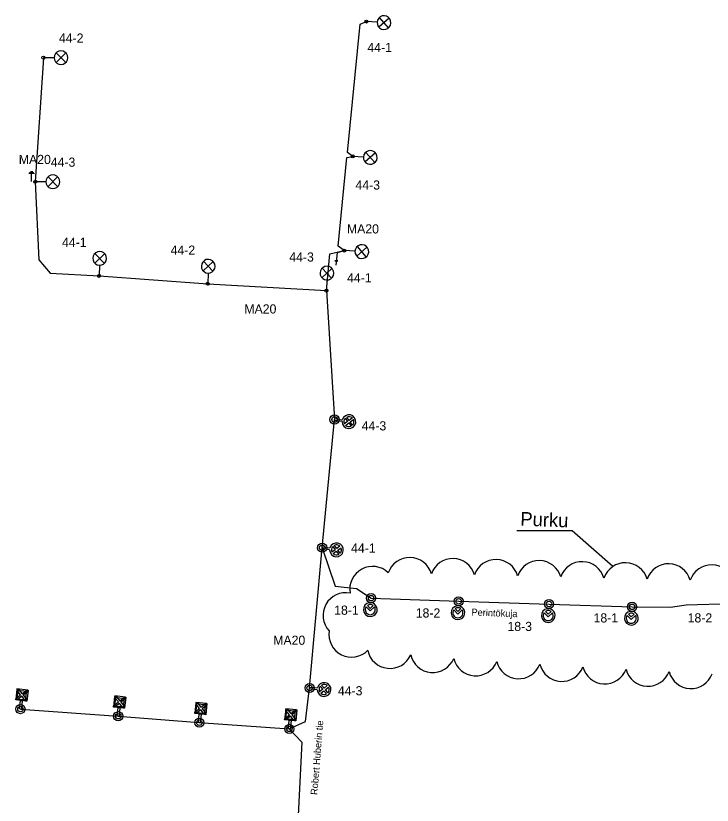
# Model space of a CAD drawing. Extents: x 25497851 to 25498523, y 6686544 to 6687372.
# Drawn here: x 25497851.1 to 25498079, y 6687110.6 to 6687368.9 of the extents above; entities that cross this region are included whole.
import ezdxf

# ---------------------------------------------------------------- set-up
doc = ezdxf.new("R2010")
doc.units = 0
for name, color, linetype in [('EL_CABLE_MAA', 7, 'Continuous'), ('KAAPELI', 7, 'Continuous'), ('KEYGWT_ANNOTATION', 7, 'Continuous'), ('Level 17', 7, 'Continuous'), ('Level 63', 7, 'Continuous'), ('MUU_SUUNNITELMAVIIVA', 7, 'Continuous'), ('PYLVAS', 7, 'Continuous'), ('Taso 1', 7, 'Continuous'), ('TEKSTI_SUUNNITELMA-ALUE', 7, 'Continuous'), ('VALAISIN', 7, 'Continuous'), ('VIITEVIIVA', 7, 'Continuous')]:
    doc.layers.add(name, color=color, linetype=linetype)

msp = doc.modelspace()

# ---------------------------------------------------------------- linework, layer by layer
at = {"layer": 'EL_CABLE_MAA'}
for points in [[(25497961.39, 6687322.89), (25497959.67, 6687324.13), (25497963.77, 6687366.17), (25497965.87, 6687367.01)], [(25497860.17, 6687355.18), (25497857.52, 6687314.58)], [(25497958.62, 6687292.08), (25497956.57, 6687293.5), (25497959.48, 6687322.57), (25497961.39, 6687322.89)], [(25497857.52, 6687314.58), (25497858.66, 6687289.03), (25497862.4, 6687284.66), (25497878.39, 6687283.78)], [(25497952.75, 6687278.97), (25497953.92, 6687291), (25497958.62, 6687292.08)], [(25497955.97, 6687287.26), (25497956.36, 6687291.42), (25497958.62, 6687292.08)], [(25497878.39, 6687283.78), (25497913.92, 6687281.21)], [(25497913.92, 6687281.21), (25497952.75, 6687278.97)], [(25497952.75, 6687278.97), (25497955.43, 6687236.8)], [(25497951.39, 6687194.86), (25497955.65, 6687182.29), (25497962.62, 6687181.52), (25497967.39, 6687178.33)], [(25497967.39, 6687178.33), (25497996.06, 6687177.32)], [(25497996.06, 6687177.32), (25498025.62, 6687176.4)], [(25498025.62, 6687176.4), (25498052.78, 6687175.51)], [(25498052.78, 6687175.51), (25498065.4, 6687175.42), (25498070.51, 6687176.14), (25498085.44, 6687176.58)]]:
    msp.add_lwpolyline(points, dxfattribs=at)
at = {"layer": 'KAAPELI'}
for p, q in [((25497951.39, 6687194.86), (25497955.43, 6687236.8)), ((25497947.28, 6687148.96), (25497951.39, 6687194.86)), ((25497852.66, 6687142.04), (25497884.63, 6687139.71)), ((25497884.63, 6687139.71), (25497911.19, 6687137.62)), ((25497911.19, 6687137.62), (25497940.63, 6687135.56))]:
    msp.add_line(p, q, dxfattribs=at)
for points in [[(25497940.63, 6687135.56), (25497945.95, 6687138.02), (25497947.28, 6687148.96)], [(25497940.63, 6687135.56), (25497944.75, 6687131.17), (25497943.46, 6687105.16)]]:
    msp.add_lwpolyline(points, dxfattribs=at)
at = {"layer": 'Level 17'}
for points in [[(25497855.37, 6687317.37), (25497856.31, 6687317.36)], [(25497855.66, 6687317.62), (25497856.33, 6687317.61)], [(25497856.33, 6687317.87), (25497855.96, 6687317.88)], [(25497856.28, 6687314.62), (25497856.32, 6687317.35)], [(25497856.31, 6687317.36), (25497857.26, 6687317.34)], [(25497856.71, 6687317.87), (25497856.33, 6687317.87)], [(25497856.33, 6687317.61), (25497857, 6687317.6)]]:
    msp.add_lwpolyline(points, dxfattribs=at)
at = {"layer": 'MUU_SUUNNITELMAVIIVA'}
for centre, start, end in [((25497980, 6687184.25), 16.1186, 161.1186), ((25497994.11, 6687183.91), 16.1119, 161.1119), ((25498008.23, 6687183.57), 16.1104, 161.1104), ((25498022.35, 6687183.23), 16.1096, 161.1096), ((25498036.46, 6687182.88), 16.1092, 161.1092), ((25497967.82, 6687181.35), 45.652, 190.652), ((25498050.58, 6687182.54), 16.1088, 161.1088), ((25498064.69, 6687182.2), 16.1085, 161.1085), ((25498078.81, 6687181.85), 16.1083, 161.1083), ((25497959.07, 6687172.73), 78.5211, 223.5211), ((25497961.01, 6687166.44), 170.7281, 315.7281), ((25497973.56, 6687162.74), 191.4587, 336.4587), ((25497987.57, 6687161.42), 192.7513, 337.7513), ((25498001.62, 6687160.33), 193.3921, 338.3921), ((25498015.69, 6687159.37), 193.7941, 338.7941), ((25498029.78, 6687158.49), 194.0765, 339.0765), ((25498043.87, 6687157.68), 194.2891, 339.2891), ((25498057.96, 6687156.91), 194.4565, 339.4565), ((25498072.05, 6687156.17), 194.5929, 339.5929)]:
    msp.add_arc(centre, 7.4, start, end, dxfattribs=at)
at = {"layer": 'PYLVAS'}
for centre, radius in [((25497955.43, 6687236.8), 1.5), ((25497955.43, 6687236.8), 0.9), ((25497951.39, 6687194.86), 1.5), ((25497951.39, 6687194.86), 0.9), ((25497967.39, 6687178.33), 1.5), ((25497967.39, 6687178.33), 0.9), ((25497996.06, 6687177.32), 1.5), ((25497996.06, 6687177.32), 0.9), ((25498025.6, 6687176.43), 1.5), ((25498025.6, 6687176.43), 0.9), ((25498052.78, 6687175.51), 1.5), ((25498052.78, 6687175.51), 0.9), ((25497947.28, 6687148.96), 1.5), ((25497947.28, 6687148.96), 0.9), ((25497852.66, 6687142.04), 1.5), ((25497852.66, 6687142.04), 0.9), ((25497884.63, 6687139.71), 1.5), ((25497884.63, 6687139.71), 0.9), ((25497911.19, 6687137.62), 1.5), ((25497911.19, 6687137.62), 0.9), ((25497940.63, 6687135.56), 1.5), ((25497940.63, 6687135.56), 0.9)]:
    msp.add_circle(centre, radius, dxfattribs=at)
at = {"layer": 'Taso 1'}
for p, q in [((25497973.08, 6687364.98), (25497970.14, 6687368.31)), ((25497969.36, 6687366.79), (25497965.87, 6687367.01)), ((25497973.27, 6687368.12), (25497969.94, 6687365.18)), ((25497867.49, 6687356.75), (25497864.35, 6687353.61)), ((25497867.49, 6687353.61), (25497864.35, 6687356.75)), ((25497863.67, 6687355.18), (25497860.17, 6687355.18)), ((25497964.88, 6687322.67), (25497961.39, 6687322.89)), ((25497968.79, 6687324), (25497965.46, 6687321.06)), ((25497968.6, 6687320.87), (25497965.66, 6687324.2)), ((25497861.02, 6687314.58), (25497857.52, 6687314.58)), ((25497864.84, 6687316.15), (25497861.7, 6687313)), ((25497864.84, 6687313), (25497861.7, 6687316.15)), ((25497965.83, 6687290.06), (25497962.89, 6687293.39)), ((25497880.19, 6687291.04), (25497876.95, 6687288)), ((25497877.05, 6687291.14), (25497880.1, 6687287.9)), ((25497962.12, 6687291.87), (25497958.62, 6687292.08)), ((25497966.03, 6687293.19), (25497962.7, 6687290.25)), ((25497915.72, 6687288.47), (25497912.48, 6687285.43)), ((25497912.58, 6687288.57), (25497915.62, 6687285.33)), ((25497955.49, 6687288.7), (25497956.46, 6687288.64)), ((25497955.5, 6687288.84), (25497956.47, 6687288.78)), ((25497878.5, 6687287.27), (25497878.39, 6687283.78)), ((25497954.55, 6687286.23), (25497951.31, 6687283.19)), ((25497951.41, 6687286.33), (25497954.45, 6687283.09)), ((25497914.03, 6687284.7), (25497913.92, 6687281.21)), ((25497952.86, 6687282.46), (25497952.75, 6687278.97))]:
    msp.add_line(p, q, dxfattribs=at)
for points in [[(25497973.85, 6687366.51), (25497973.79, 6687367.21), (25497973.51, 6687367.85), (25497973.04, 6687368.38), (25497972.43, 6687368.74), (25497971.75, 6687368.89), (25497971.05, 6687368.83), (25497970.4, 6687368.55), (25497969.87, 6687368.08), (25497969.52, 6687367.48), (25497969.36, 6687366.79), (25497969.43, 6687366.09), (25497969.71, 6687365.44), (25497970.17, 6687364.91), (25497970.78, 6687364.56), (25497971.47, 6687364.4), (25497972.17, 6687364.47), (25497972.81, 6687364.75), (25497973.34, 6687365.21), (25497973.7, 6687365.82)], [(25497868.17, 6687355.18), (25497868.06, 6687355.87), (25497867.74, 6687356.5), (25497867.24, 6687357), (25497866.62, 6687357.32), (25497865.92, 6687357.43), (25497865.23, 6687357.32), (25497864.6, 6687357), (25497864.1, 6687356.5), (25497863.78, 6687355.87), (25497863.67, 6687355.18), (25497863.78, 6687354.48), (25497864.1, 6687353.86), (25497864.6, 6687353.36), (25497865.23, 6687353.04), (25497865.92, 6687352.93), (25497866.62, 6687353.04), (25497867.24, 6687353.36), (25497867.74, 6687353.86), (25497868.06, 6687354.48)], [(25497969.37, 6687322.39), (25497969.3, 6687323.09), (25497969.02, 6687323.74), (25497968.56, 6687324.27), (25497967.95, 6687324.62), (25497967.27, 6687324.78), (25497966.57, 6687324.71), (25497965.92, 6687324.43), (25497965.39, 6687323.97), (25497965.03, 6687323.36), (25497964.88, 6687322.67), (25497964.95, 6687321.97), (25497965.23, 6687321.33), (25497965.69, 6687320.8), (25497966.3, 6687320.44), (25497966.98, 6687320.29), (25497967.68, 6687320.35), (25497968.33, 6687320.63), (25497968.86, 6687321.1), (25497969.22, 6687321.7)], [(25497865.52, 6687314.58), (25497865.41, 6687315.27), (25497865.09, 6687315.9), (25497864.59, 6687316.4), (25497863.96, 6687316.72), (25497863.27, 6687316.83), (25497862.57, 6687316.72), (25497861.95, 6687316.4), (25497861.45, 6687315.9), (25497861.13, 6687315.27), (25497861.02, 6687314.58), (25497861.13, 6687313.88), (25497861.45, 6687313.25), (25497861.95, 6687312.76), (25497862.57, 6687312.44), (25497863.27, 6687312.33), (25497863.96, 6687312.44), (25497864.59, 6687312.76), (25497865.09, 6687313.25), (25497865.41, 6687313.88)], [(25497966.61, 6687291.58), (25497966.54, 6687292.28), (25497966.26, 6687292.93), (25497965.8, 6687293.46), (25497965.19, 6687293.82), (25497964.5, 6687293.97), (25497963.8, 6687293.9), (25497963.16, 6687293.62), (25497962.63, 6687293.16), (25497962.27, 6687292.55), (25497962.12, 6687291.87), (25497962.18, 6687291.16), (25497962.46, 6687290.52), (25497962.93, 6687289.99), (25497963.53, 6687289.63), (25497964.22, 6687289.48), (25497964.92, 6687289.54), (25497965.57, 6687289.82), (25497966.09, 6687290.29), (25497966.45, 6687290.9)], [(25497878.65, 6687291.77), (25497877.95, 6687291.68), (25497877.31, 6687291.38), (25497876.8, 6687290.9), (25497876.46, 6687290.28), (25497876.33, 6687289.59), (25497876.41, 6687288.9), (25497876.71, 6687288.26), (25497877.2, 6687287.75), (25497877.81, 6687287.41), (25497878.5, 6687287.27), (25497879.2, 6687287.36), (25497879.84, 6687287.66), (25497880.35, 6687288.14), (25497880.69, 6687288.76), (25497880.82, 6687289.45), (25497880.74, 6687290.15), (25497880.44, 6687290.79), (25497879.95, 6687291.3), (25497879.34, 6687291.64)], [(25497914.17, 6687289.2), (25497913.47, 6687289.11), (25497912.83, 6687288.81), (25497912.32, 6687288.33), (25497911.98, 6687287.71), (25497911.85, 6687287.02), (25497911.94, 6687286.33), (25497912.24, 6687285.69), (25497912.72, 6687285.18), (25497913.33, 6687284.84), (25497914.03, 6687284.7), (25497914.72, 6687284.79), (25497915.36, 6687285.09), (25497915.87, 6687285.57), (25497916.21, 6687286.19), (25497916.35, 6687286.88), (25497916.26, 6687287.58), (25497915.96, 6687288.22), (25497915.48, 6687288.73), (25497914.86, 6687289.07)], [(25497953, 6687286.96), (25497952.3, 6687286.87), (25497951.66, 6687286.57), (25497951.15, 6687286.09), (25497950.81, 6687285.47), (25497950.68, 6687284.78), (25497950.77, 6687284.08), (25497951.07, 6687283.45), (25497951.55, 6687282.93), (25497952.17, 6687282.6), (25497952.86, 6687282.46), (25497953.56, 6687282.55), (25497954.19, 6687282.85), (25497954.71, 6687283.33), (25497955.05, 6687283.95), (25497955.18, 6687284.64), (25497955.09, 6687285.34), (25497954.79, 6687285.98), (25497954.31, 6687286.49), (25497953.69, 6687286.83)]]:
    msp.add_lwpolyline(points, close=True, dxfattribs=at)
for centre in [(25497965.87, 6687367.01), (25497860.17, 6687355.18), (25497961.39, 6687322.89), (25497857.52, 6687314.58), (25497958.62, 6687292.08), (25497878.39, 6687283.78), (25497913.92, 6687281.21), (25497952.75, 6687278.97)]:
    msp.add_circle(centre, 0.5, dxfattribs=at)
at = {"layer": 'VALAISIN'}
for p, q in [((25497955.39, 6687236.51), (25497955.48, 6687237.1)), ((25497957.87, 6687236.13), (25497955.39, 6687236.51)), ((25497955.48, 6687237.1), (25497957.96, 6687236.72)), ((25497958.92, 6687237.22), (25497959.7, 6687236.15)), ((25497960.18, 6687236.5), (25497959.4, 6687237.57)), ((25497961.25, 6687237.29), (25497960.18, 6687236.5)), ((25497960.54, 6687236.02), (25497961.6, 6687236.8)), ((25497959.7, 6687236.15), (25497958.63, 6687235.37)), ((25497958.99, 6687234.88), (25497960.05, 6687235.67)), ((25497960.05, 6687235.67), (25497960.84, 6687234.6)), ((25497961.32, 6687234.95), (25497960.54, 6687236.02)), ((25497951.34, 6687194.56), (25497951.43, 6687195.16)), ((25497951.43, 6687195.16), (25497953.91, 6687194.77)), ((25497954.87, 6687195.27), (25497955.65, 6687194.2)), ((25497956.14, 6687194.56), (25497955.35, 6687195.63)), ((25497957.2, 6687195.34), (25497956.14, 6687194.56)), ((25497953.82, 6687194.18), (25497951.34, 6687194.56)), ((25497955.65, 6687194.2), (25497954.59, 6687193.42)), ((25497954.94, 6687192.94), (25497956.01, 6687193.72)), ((25497956.01, 6687193.72), (25497956.79, 6687192.65)), ((25497956.49, 6687194.08), (25497957.56, 6687194.86)), ((25497957.27, 6687193.01), (25497956.49, 6687194.08)), ((25497965.76, 6687175.52), (25497967.12, 6687174.16)), ((25497967.12, 6687175.01), (25497966.18, 6687175.94)), ((25497968.05, 6687175.94), (25497967.12, 6687175.01)), ((25497967.12, 6687174.16), (25497968.48, 6687175.52)), ((25497994.43, 6687174.51), (25497995.79, 6687173.15)), ((25497995.79, 6687174), (25497994.85, 6687174.94)), ((25497996.72, 6687174.94), (25497995.79, 6687174)), ((25497995.79, 6687173.15), (25497997.15, 6687174.51)), ((25498023.98, 6687173.59), (25498025.34, 6687172.23)), ((25498025.34, 6687173.07), (25498024.41, 6687174.01)), ((25498026.28, 6687174.01), (25498025.34, 6687173.07)), ((25498025.34, 6687172.23), (25498026.7, 6687173.59)), ((25498051.15, 6687172.7), (25498052.51, 6687171.34)), ((25498052.51, 6687172.19), (25498051.57, 6687173.13)), ((25498053.44, 6687173.13), (25498052.51, 6687172.19)), ((25498052.51, 6687171.34), (25498053.87, 6687172.7)), ((25497947.25, 6687148.66), (25497947.31, 6687149.26)), ((25497949.75, 6687148.4), (25497947.25, 6687148.66)), ((25497947.31, 6687149.26), (25497949.81, 6687148.99)), ((25497950.74, 6687149.54), (25497951.57, 6687148.51)), ((25497952.04, 6687148.88), (25497951.21, 6687149.91)), ((25497953.07, 6687149.72), (25497952.04, 6687148.88)), ((25497952.42, 6687148.42), (25497953.45, 6687149.25)), ((25497951.57, 6687148.51), (25497950.55, 6687147.68)), ((25497950.92, 6687147.21), (25497951.95, 6687148.04)), ((25497951.95, 6687148.04), (25497952.78, 6687147.01)), ((25497953.25, 6687147.39), (25497952.42, 6687148.42))]:
    msp.add_line(p, q, dxfattribs=at)
for points in [[(25497854.99, 6687147.89), (25497855.03, 6687148.29), (25497851.52, 6687148.66), (25497851.48, 6687148.26)], [(25497851.51, 6687148.54), (25497851.15, 6687145.16), (25497851.55, 6687145.11), (25497851.91, 6687148.5)], [(25497854.24, 6687144.83), (25497853.1, 6687146.23), (25497851.7, 6687145.1), (25497851.28, 6687145.14), (25497851.32, 6687145.57), (25497852.73, 6687146.7), (25497851.59, 6687148.1), (25497851.63, 6687148.53), (25497852.05, 6687148.48), (25497853.19, 6687147.08), (25497854.6, 6687148.21), (25497855.02, 6687148.17), (25497854.97, 6687147.75), (25497853.57, 6687146.61), (25497854.71, 6687145.21), (25497854.66, 6687144.79)], [(25497854.37, 6687144.69), (25497854.75, 6687148.32), (25497855.15, 6687148.28), (25497854.77, 6687144.65)], [(25497883.49, 6687146.21), (25497883.13, 6687142.83), (25497883.53, 6687142.78), (25497883.88, 6687146.17)], [(25497886.22, 6687142.5), (25497885.08, 6687143.9), (25497883.67, 6687142.77), (25497883.25, 6687142.81), (25497883.3, 6687143.23), (25497884.7, 6687144.37), (25497883.56, 6687145.77), (25497883.61, 6687146.2), (25497884.03, 6687146.15), (25497885.17, 6687144.75), (25497886.57, 6687145.88), (25497887, 6687145.84), (25497886.95, 6687145.42), (25497885.55, 6687144.28), (25497886.68, 6687142.88), (25497886.64, 6687142.46)], [(25497886.97, 6687145.56), (25497887.01, 6687145.96), (25497883.5, 6687146.33), (25497883.46, 6687145.93)], [(25497851.14, 6687145.04), (25497851.18, 6687145.43), (25497854.69, 6687145.06), (25497854.65, 6687144.66)], [(25497852.36, 6687142.08), (25497852.66, 6687144.88), (25497853.25, 6687144.81), (25497852.96, 6687142.01)], [(25497886.35, 6687142.36), (25497886.73, 6687145.99), (25497887.13, 6687145.95), (25497886.75, 6687142.32)], [(25497910.04, 6687144.11), (25497909.69, 6687140.73), (25497910.08, 6687140.69), (25497910.44, 6687144.07)], [(25497912.77, 6687140.4), (25497911.64, 6687141.81), (25497910.23, 6687140.67), (25497909.81, 6687140.71), (25497909.85, 6687141.14), (25497911.26, 6687142.27), (25497910.12, 6687143.68), (25497910.16, 6687144.1), (25497910.59, 6687144.05), (25497911.72, 6687142.65), (25497913.13, 6687143.78), (25497913.55, 6687143.74), (25497913.51, 6687143.32), (25497912.1, 6687142.18), (25497913.24, 6687140.78), (25497913.2, 6687140.36)], [(25497913.52, 6687143.46), (25497913.57, 6687143.86), (25497910.06, 6687144.23), (25497910.01, 6687143.83)], [(25497912.9, 6687140.26), (25497913.29, 6687143.89), (25497913.69, 6687143.85), (25497913.3, 6687140.22)], [(25497883.12, 6687142.7), (25497883.16, 6687143.1), (25497886.67, 6687142.73), (25497886.63, 6687142.33)], [(25497884.34, 6687139.75), (25497884.63, 6687142.54), (25497885.23, 6687142.48), (25497884.93, 6687139.68)], [(25497909.67, 6687140.61), (25497909.72, 6687141), (25497913.22, 6687140.63), (25497913.18, 6687140.24)], [(25497939.44, 6687142.05), (25497939.11, 6687138.66), (25497939.5, 6687138.62), (25497939.84, 6687142.01)], [(25497942.19, 6687138.36), (25497941.05, 6687139.75), (25497939.65, 6687138.61), (25497939.23, 6687138.65), (25497939.27, 6687139.07), (25497940.67, 6687140.22), (25497939.52, 6687141.61), (25497939.56, 6687142.03), (25497939.98, 6687141.99), (25497941.13, 6687140.6), (25497942.53, 6687141.74), (25497942.95, 6687141.7), (25497942.91, 6687141.28), (25497941.51, 6687140.13), (25497942.66, 6687138.74), (25497942.62, 6687138.32)], [(25497942.92, 6687141.42), (25497942.96, 6687141.82), (25497939.45, 6687142.17), (25497939.41, 6687141.77)], [(25497942.33, 6687138.22), (25497942.68, 6687141.85), (25497943.08, 6687141.81), (25497942.72, 6687138.18)], [(25497910.89, 6687137.65), (25497911.19, 6687140.45), (25497911.78, 6687140.38), (25497911.49, 6687137.58)], [(25497939.09, 6687138.54), (25497939.13, 6687138.94), (25497942.64, 6687138.59), (25497942.6, 6687138.19)], [(25497940.33, 6687135.59), (25497940.61, 6687138.39), (25497941.21, 6687138.33), (25497940.93, 6687135.53)]]:
    msp.add_lwpolyline(points, close=True, dxfattribs=at)
for centre, radius, start, end in [((25497960.12, 6687236.09), 2.25, 351.2726, 163.6103), ((25497960.12, 6687236.09), 1.65, 136.7482, 171.2726), ((25497960.12, 6687236.09), 1.65, 46.7482, 115.7969), ((25497960.12, 6687236.09), 1.65, 351.2726, 25.7969), ((25497960.12, 6687236.09), 2.25, 178.9348, 351.2726), ((25497960.12, 6687236.09), 1.65, 171.2726, 205.7969), ((25497960.12, 6687236.09), 1.65, 226.7482, 295.7969), ((25497960.12, 6687236.09), 1.65, 316.7482, 351.2726), ((25497956.07, 6687194.14), 2.25, 351.2726, 163.6103), ((25497956.07, 6687194.14), 1.65, 136.7482, 171.2726), ((25497956.07, 6687194.14), 1.65, 46.7482, 115.7969), ((25497956.07, 6687194.14), 2.25, 178.9348, 351.2726), ((25497956.07, 6687194.14), 1.65, 171.2726, 205.7969), ((25497956.07, 6687194.14), 1.65, 226.7482, 295.7969), ((25497956.07, 6687194.14), 1.65, 316.7482, 351.2726), ((25497956.07, 6687194.14), 1.65, 351.2726, 25.7969), ((25497967.12, 6687174.59), 2.25, 97.6623, 270), ((25497967.12, 6687174.59), 1.65, 145.4757, 270), ((25497967.12, 6687174.59), 1.65, 90, 124.5243), ((25497967.12, 6687174.59), 2.25, 270, 97.6623), ((25497967.12, 6687174.59), 1.65, 55.4757, 90), ((25497967.12, 6687174.59), 1.65, 270, 34.5243), ((25497995.79, 6687173.58), 2.25, 97.6623, 270), ((25497995.79, 6687173.58), 1.65, 145.4757, 270), ((25497995.79, 6687173.58), 1.65, 90, 124.5243), ((25497995.79, 6687173.58), 2.25, 270, 97.6623), ((25497995.79, 6687173.58), 1.65, 55.4757, 90), ((25497995.79, 6687173.58), 1.65, 270, 34.5243), ((25498025.34, 6687172.65), 2.25, 97.6623, 270), ((25498025.34, 6687172.65), 2.25, 270, 97.6623), ((25498025.34, 6687172.65), 1.65, 145.4757, 270), ((25498025.34, 6687172.65), 1.65, 90, 124.5243), ((25498025.34, 6687172.65), 1.65, 55.4757, 90), ((25498025.34, 6687172.65), 1.65, 270, 34.5243), ((25498052.51, 6687171.77), 2.25, 97.6623, 270), ((25498052.51, 6687171.77), 1.65, 145.4757, 270), ((25498052.51, 6687171.77), 1.65, 90, 124.5243), ((25498052.51, 6687171.77), 2.25, 270, 97.6623), ((25498052.51, 6687171.77), 1.65, 55.4757, 90), ((25498052.51, 6687171.77), 1.65, 270, 34.5243), ((25497952, 6687148.46), 2.25, 353.991, 166.3287), ((25497952, 6687148.46), 1.65, 139.4667, 173.991), ((25497952, 6687148.46), 1.65, 49.4667, 118.5153), ((25497952, 6687148.46), 1.65, 353.991, 28.5153), ((25497952, 6687148.46), 2.25, 181.6533, 353.991), ((25497952, 6687148.46), 1.65, 173.991, 208.5153), ((25497952, 6687148.46), 1.65, 229.4667, 298.5153), ((25497952, 6687148.46), 1.65, 319.4667, 353.991)]:
    msp.add_arc(centre, radius, start, end, dxfattribs=at)
at = {"layer": 'VIITEVIIVA'}
msp.add_lwpolyline([(25498015.1, 6687200.53), (25498033.17, 6687200.53), (25498046.52, 6687188.77)], dxfattribs=at)

# ---------------------------------------------------------------- texts
at = {"layer": 'KEYGWT_ANNOTATION'}
for s, p in [('44-2', (25497865.25, 6687360.1)), ('44-1', (25497966.17, 6687357.03)), ('MA20', (25497852.13, 6687320.39)), ('44-3', (25497862.59, 6687319.5)), ('44-3', (25497962.28, 6687312.03)), ('MA20', (25497959.48, 6687297.67)), ('44-1', (25497866.26, 6687293.28)), ('44-2', (25497901.79, 6687290.71)), ('44-3', (25497940.62, 6687288.47)), ('44-1', (25497959.52, 6687281.65)), ('MA20', (25497925.92, 6687271.48)), ('44-3', (25497964.31, 6687233.22)), ('44-1', (25497960.84, 6687193.23)), ('18-1', (25497955.31, 6687172.91)), ('18-2', (25497982, 6687172)), ('18-1', (25498040.18, 6687170.38)), ('18-2', (25498070.96, 6687170.39)), ('18-3', (25498012, 6687167.59)), ('MA20', (25497935.37, 6687163.08)), ('44-3', (25497956.53, 6687146.54))]:
    msp.add_text(s, height=3, dxfattribs=at).set_placement(p)
at = {"layer": 'Level 63'}
msp.add_text('(C) KEYPRO 2000', height=0.0001, rotation=179.1, dxfattribs=at).set_placement((25497856.71, 6687317.87))
at = {"layer": 'TEKSTI_SUUNNITELMA-ALUE'}
for s, rotation, p in [('Perintökuja', 357.849, (25498000.21, 6687172.67)), ('Robert Huberin tie', 85.3437, (25497949.8, 6687113.89))]:
    msp.add_text(s, height=2.25, rotation=rotation, dxfattribs=at).set_placement(p)
at = {"layer": 'VIITEVIIVA'}
msp.add_text('Purku', height=4.5, rotation=357.849, dxfattribs=at).set_placement((25498016.15, 6687202.08))

doc.saveas('drawing.dxf')
